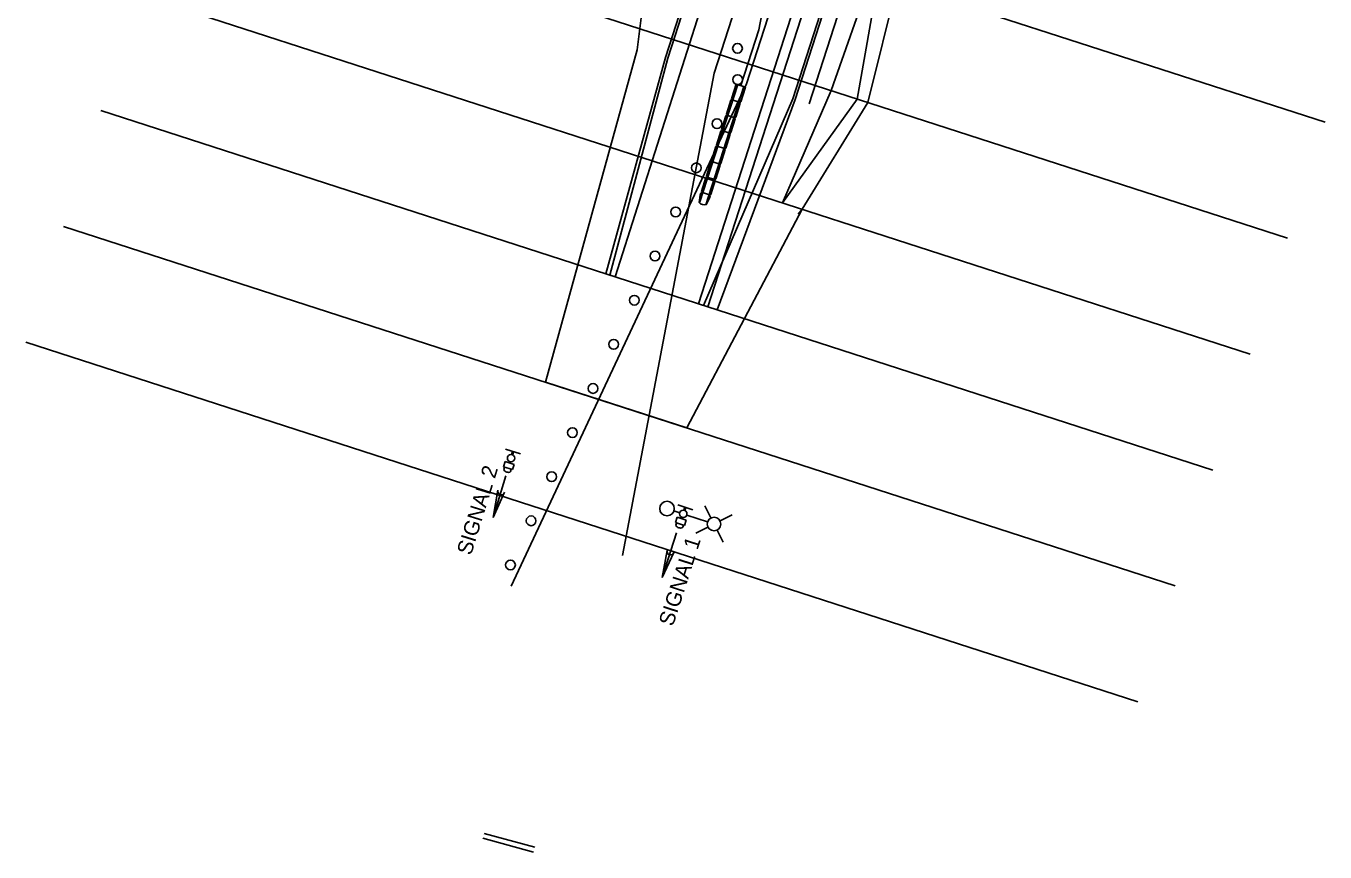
# Model space of a CAD drawing. Extents: x 157201 to 163282, y 424960 to 427200.
# Drawn here: x 157201 to 157467.8, y 426058.7 to 426228.2 of the extents above; entities that cross this region are included whole.
import ezdxf

# ---------------------------------------------------------------- set-up
doc = ezdxf.new("R2010")
doc.units = 0
for name, color, linetype in [('Default', 7, 'Continuous'), ('DR_X_Text', 7, 'Continuous'), ('GE_P_Alignment', 7, 'Continuous'), ('PV_X_COP', 7, 'Continuous'), ('RD_X_Gate', 7, 'Continuous'), ('RW_X_CL_100_Curve_Data', 7, 'Continuous'), ('RW_X_CL_100_Distances', 7, 'Continuous'), ('RW_X_CL_100_Stations', 7, 'Continuous'), ('SC_Scratch1', 7, 'Continuous'), ('SN_X_Public', 7, 'Continuous')]:
    doc.layers.add(name, color=color, linetype=linetype)

msp = doc.modelspace()

# ---------------------------------------------------------------- linework, layer by layer
at = {"layer": 'Default'}
for p, q in [((157239.43, 426282.25), (157467.81, 426208.46)), ((157231.75, 426258.46), (157460.12, 426184.67)), ((157224.06, 426234.67), (157452.43, 426160.88)), ((157216.37, 426210.88), (157444.75, 426137.09)), ((157208.69, 426187.09), (157437.06, 426113.3)), ((157201, 426163.3), (157429.38, 426089.51))]:
    msp.add_line(p, q, dxfattribs=at)
at = {"layer": 'DR_X_Text'}
msp.add_lwpolyline([(157356.39, 426191.91), (157366.36, 426214.96), (157374.68, 426238.55), (157383.02, 426262.13), (157391.18, 426285.33), (157399.37, 426308.95), (157406.74, 426321.52)], dxfattribs=at)
at = {"layer": 'GE_P_Alignment'}
for p, q in [((157342.93, 426169.99), (157358.98, 426213.15)), ((157341.03, 426170.6), (157342.93, 426169.99))]:
    msp.add_line(p, q, dxfattribs=at)
msp.add_lwpolyline([(157414.47, 426379.12), (157381.59, 426283.12), (157358.98, 426213.15)], dxfattribs=at)
at = {"layer": 'PV_X_COP'}
for p, q in [((157305.23, 426058.7), (157294.83, 426061.53)), ((157295.09, 426062.5), (157305.49, 426059.67))]:
    msp.add_line(p, q, dxfattribs=at)
at = {"layer": 'RD_X_Gate'}
for points in [[(157361.83, 426212.22), (157384.43, 426282.17), (157398.79, 426324.1)], [(157356.39, 426191.91), (157371.74, 426213.23), (157376.12, 426238.08), (157384.6, 426261.61), (157393.32, 426284.6), (157402.88, 426307.75)]]:
    msp.add_lwpolyline(points, dxfattribs=at)
at = {"layer": 'RW_X_CL_100_Curve_Data'}
for p, q in [((157369.87, 426266.37), (157339.12, 426171.22)), ((157339.12, 426171.22), (157341.03, 426170.6))]:
    msp.add_line(p, q, dxfattribs=at)
msp.add_lwpolyline([(157410.68, 426380.42), (157377.79, 426284.38), (157341.03, 426170.6)], dxfattribs=at)
at = {"layer": 'RW_X_CL_100_Distances'}
for p, q in [((157300.67, 426113.23), (157348.99, 426216.37)), ((157358.5, 426213.3), (157340.14, 426170.89))]:
    msp.add_line(p, q, dxfattribs=at)
for points in [[(157404.53, 426382.52), (157371.62, 426286.44), (157348.99, 426216.37)], [(157358.5, 426213.3), (157381.11, 426283.28), (157413.99, 426379.28)]]:
    msp.add_lwpolyline(points, dxfattribs=at)
for centre in [(157347.14, 426223.63), (157347.17, 426217.22), (157342.93, 426208.17), (157338.69, 426199.11), (157334.45, 426190.06), (157330.21, 426181), (157325.96, 426171.94), (157321.72, 426162.89), (157317.48, 426153.83), (157313.24, 426144.78), (157308.99, 426135.72), (157304.75, 426126.67), (157300.51, 426117.61)]:
    msp.add_circle(centre, 1, dxfattribs=at)
at = {"layer": 'RW_X_CL_100_Stations'}
for p, q in [((157358.2, 426262.79), (157351.5, 426227.42)), ((157351.5, 426227.42), (157347.81, 426216)), ((157320.93, 426177.1), (157332.81, 426221.6)), ((157323.49, 426119.52), (157342.32, 426218.53)), ((157339.34, 426191.95), (157347.18, 426216.2)), ((157348.45, 426215.79), (157340.61, 426191.54)), ((157345.89, 426213.29), (157346.86, 426216.3)), ((157348.77, 426215.69), (157346.86, 426216.3)), ((157347.79, 426212.68), (157348.77, 426215.69)), ((157346, 426213.08), (157345.79, 426212.97)), ((157345.89, 426213.29), (157346, 426213.08)), ((157347.58, 426212.57), (157346, 426213.08)), ((157344.86, 426210.12), (157345.79, 426212.97)), ((157346.77, 426209.5), (157347.69, 426212.36)), ((157347.79, 426212.68), (157347.58, 426212.57)), ((157347.58, 426212.57), (157347.69, 426212.36)), ((157343.84, 426206.95), (157344.76, 426209.8)), ((157344.97, 426209.91), (157344.76, 426209.8)), ((157344.86, 426210.12), (157344.97, 426209.91)), ((157346.56, 426209.4), (157344.97, 426209.91)), ((157345.74, 426206.33), (157346.67, 426209.19)), ((157346.77, 426209.5), (157346.56, 426209.4)), ((157346.56, 426209.4), (157346.67, 426209.19)), ((157342.82, 426203.78), (157343.74, 426206.63)), ((157343.95, 426206.74), (157343.74, 426206.63)), ((157343.84, 426206.95), (157343.95, 426206.74)), ((157345.53, 426206.23), (157343.95, 426206.74)), ((157344.72, 426203.16), (157345.64, 426206.02)), ((157345.74, 426206.33), (157345.53, 426206.23)), ((157345.53, 426206.23), (157345.64, 426206.02)), ((157341.79, 426200.6), (157342.71, 426203.46)), ((157342.92, 426203.57), (157342.71, 426203.46)), ((157342.82, 426203.78), (157342.92, 426203.57)), ((157344.51, 426203.05), (157342.92, 426203.57)), ((157343.69, 426199.99), (157344.62, 426202.84)), ((157344.72, 426203.16), (157344.51, 426203.05)), ((157344.51, 426203.05), (157344.62, 426202.84)), ((157340.77, 426197.43), (157341.69, 426200.29)), ((157341.9, 426200.39), (157341.69, 426200.29)), ((157341.79, 426200.6), (157341.9, 426200.39)), ((157343.48, 426199.88), (157341.9, 426200.39)), ((157343.69, 426199.99), (157343.48, 426199.88)), ((157343.48, 426199.88), (157343.59, 426199.67)), ((157339.74, 426194.26), (157340.66, 426197.12)), ((157340.87, 426197.22), (157340.66, 426197.12)), ((157340.77, 426197.43), (157340.87, 426197.22)), ((157342.46, 426196.71), (157340.87, 426197.22)), ((157343.59, 426199.67), (157342.67, 426196.82)), ((157342.57, 426196.5), (157341.64, 426193.65)), ((157342.67, 426196.82), (157342.46, 426196.71)), ((157342.46, 426196.71), (157342.57, 426196.5)), ((157339.5, 426193.53), (157339.28, 426192.02)), ((157339.5, 426193.53), (157339.64, 426193.94)), ((157339.85, 426194.05), (157339.64, 426193.94)), ((157339.74, 426194.26), (157339.85, 426194.05)), ((157341.43, 426193.54), (157339.85, 426194.05)), ((157341.41, 426192.91), (157340.71, 426191.56)), ((157341.54, 426193.33), (157341.41, 426192.91)), ((157341.64, 426193.65), (157341.43, 426193.54)), ((157341.43, 426193.54), (157341.54, 426193.33))]:
    msp.add_line(p, q, dxfattribs=at)
for points in [[(157342.32, 426218.53), (157364.98, 426288.65), (157393.34, 426371.45)], [(157375.4, 426349.93), (157355.49, 426291.81), (157332.81, 426221.6)]]:
    msp.add_lwpolyline(points, dxfattribs=at)
msp.add_arc((157340.33, 426192.84), 1.34, 217.9187, 286.27, dxfattribs=at)
at = {"layer": 'SC_Scratch1'}
for p, q in [((157326.55, 426223.35), (157307.73, 426155.09)), ((157360.39, 426190.62), (157359.63, 426189.57)), ((157299.5, 426141.34), (157302.6, 426140.39)), ((157299.07, 426137.74), (157299.41, 426138.84)), ((157299.41, 426138.84), (157301.26, 426138.26)), ((157300.3, 426138.84), (157300.22, 426138.58)), ((157300.53, 426138.77), (157300.45, 426138.51)), ((157300.93, 426140.9), (157300.74, 426140.27)), ((157301.16, 426140.83), (157300.97, 426140.2)), ((157299.58, 426135.9), (157296.93, 426127.35)), ((157299.07, 426137.74), (157300.92, 426137.17)), ((157299.16, 426137.2), (157299.31, 426137.66)), ((157300.54, 426136.77), (157300.68, 426137.24)), ((157300.92, 426137.17), (157301.26, 426138.26)), ((157296.93, 426127.35), (157297.92, 426132.93)), ((157299.27, 426132.52), (157296.93, 426127.35)), ((157334.08, 426128.71), (157335.28, 426128.32)), ((157334.88, 426129.93), (157337.97, 426128.94)), ((157336.31, 426129.47), (157336.11, 426128.84)), ((157336.54, 426129.4), (157336.34, 426128.77)), ((157336.72, 426127.85), (157340.99, 426126.45)), ((157341.69, 426127.26), (157340.42, 426129.76)), ((157343.57, 426126.64), (157346.07, 426127.9)), ((157334.42, 426126.33), (157334.77, 426127.42)), ((157334.42, 426126.33), (157336.27, 426125.74)), ((157334.5, 426125.79), (157334.65, 426126.25)), ((157334.77, 426127.42), (157336.61, 426126.83)), ((157335.66, 426127.41), (157335.58, 426127.16)), ((157335.89, 426127.34), (157335.81, 426127.09)), ((157335.88, 426125.35), (157336.03, 426125.81)), ((157336.27, 426125.74), (157336.61, 426126.83)), ((157341.07, 426125.38), (157338.57, 426124.12)), ((157334.61, 426124.23), (157331.65, 426115.04)), ((157342.95, 426124.76), (157344.21, 426122.26)), ((157331.65, 426115.04), (157332.7, 426120.61)), ((157334.04, 426120.17), (157331.65, 426115.04))]:
    msp.add_line(p, q, dxfattribs=at)
for points in [[(157326.55, 426223.35), (157328.94, 426242.56), (157328.23, 426263.59), (157330.46, 426269.42)], [(157307.73, 426155.09), (157336.72, 426145.72), (157360.39, 426190.62), (157373.94, 426212.51), (157380, 426237.05)]]:
    msp.add_lwpolyline(points, dxfattribs=at)
for centre, radius in [((157300.63, 426139.52), 0.757), ((157332.66, 426129.18), 1.5), ((157336, 426128.09), 0.757), ((157342.32, 426126.01), 1.4)]:
    msp.add_circle(centre, radius, dxfattribs=at)
for centre, start, end in [((157298.59, 426132.72), 162.7373, 342.7373), ((157333.37, 426120.39), 162.1465, 342.1465)]:
    msp.add_arc(centre, 0.703, start, end, dxfattribs=at)
for centre, major_axis in [((157299.85, 426136.99), (-0.689, 0.213)), ((157335.19, 426125.57), (-0.686, 0.22))]:
    msp.add_ellipse(centre, major_axis=major_axis, ratio=0.45371, start_param=0, end_param=3.141593, dxfattribs=at)
at = {"layer": 'SN_X_Public'}
for p, q in [((157381.52, 426363.16), (157322, 426176.75)), ((157332.33, 426221.75), (157320.09, 426177.37)), ((157322, 426176.75), (157320.09, 426177.37))]:
    msp.add_line(p, q, dxfattribs=at)
msp.add_lwpolyline([(157379.62, 426363.81), (157355.02, 426291.96), (157332.33, 426221.75)], dxfattribs=at)

# ---------------------------------------------------------------- texts
at = {"layer": 'SC_Scratch1'}
for s, rotation, p in [('SIGNAL 2', 72.7373, (157292.4, 426119.44)), ('SIGNAL 1', 72.1465, (157333.86, 426104.86))]:
    msp.add_text(s, height=3.125, rotation=rotation, dxfattribs=at).set_placement(p)

doc.saveas('drawing.dxf')
